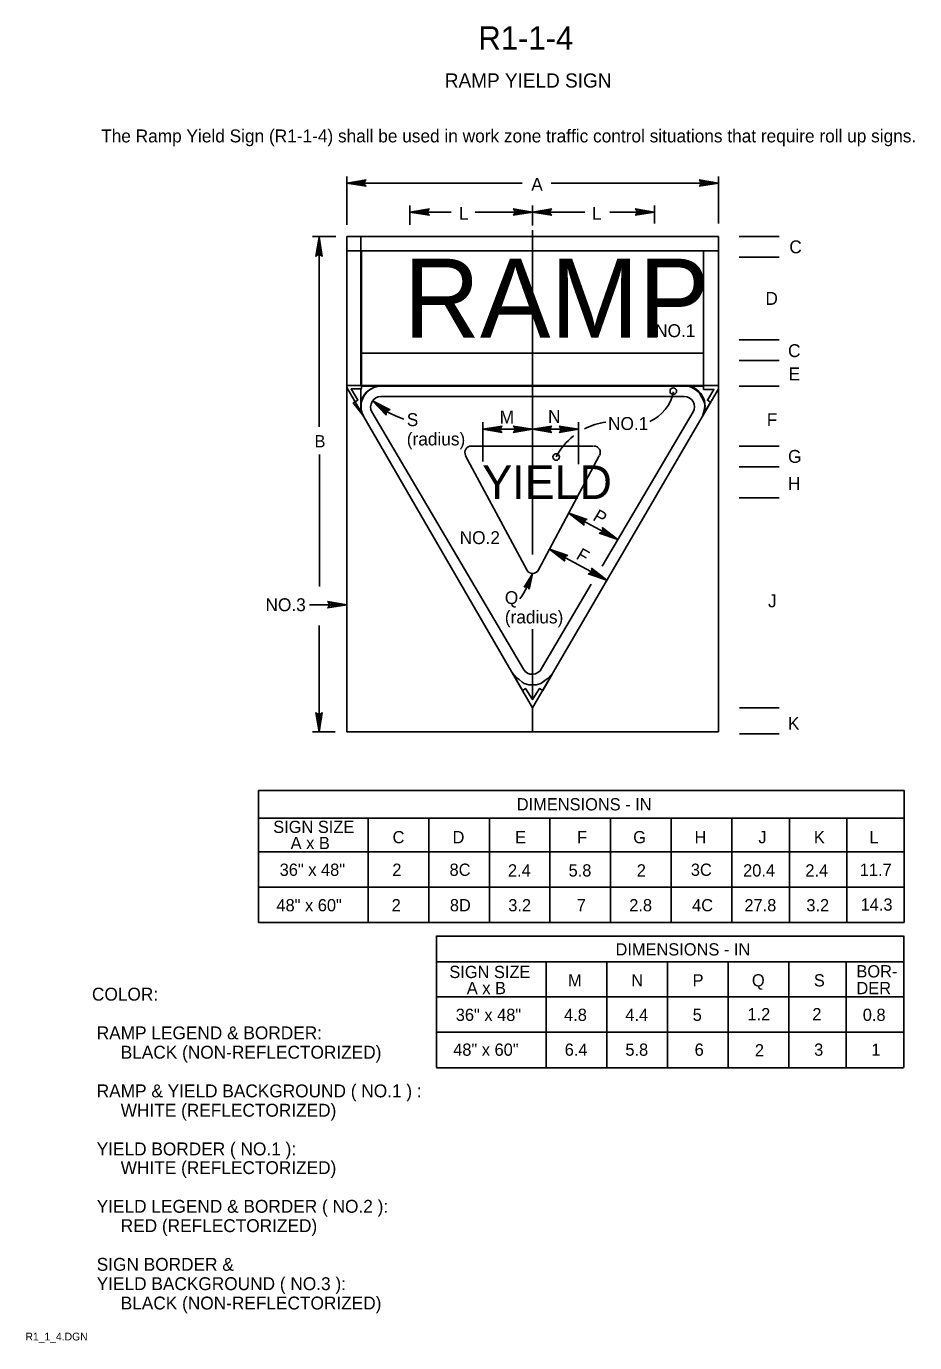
# Model space of a CAD drawing. Extents: x 0.013 to 0.185, y 0.004 to 0.259.
import ezdxf

# ---------------------------------------------------------------- set-up
doc = ezdxf.new("R2010")
doc.units = 0
for name, color, linetype in [('1', 7, 'Continuous'), ('2', 7, 'Continuous'), ('3', 7, 'Continuous')]:
    doc.layers.add(name, color=color, linetype=linetype)

# ---------------------------------------------------------------- blocks, each defined once
blk = doc.blocks.new('RARROW')
at = {"layer": '3'}
for p, q in [((-2.156, 0.28500000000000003), (-2.2665, 0.384625)), ((-2.2665, 0.384625), (0, 0)), ((0, 0), (-2.2665, -0.379125)), ((-2.156, 0.28500000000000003), (-2.075625, 0.12075)), ((0, 0), (-2.156, 0.28500000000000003)), ((-2.14975, -0.2705), (0, 0)), ((-2.075625, 0.12075), (0, 0)), ((0, 0), (-2.074, -0.108)), ((-2.2665, -0.379125), (-2.14975, -0.2705)), ((-2.074, -0.108), (-2.14975, -0.2705))]:
    blk.add_line(p, q, dxfattribs=at)

msp = doc.modelspace()

# ---------------------------------------------------------------- linework, layer by layer
at = {"layer": '1'}
for p, q in [((0.110625, 0.21962500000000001), (0.110625, 0.15675)), ((0.101, 0.182375), (0.101, 0.17475000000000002)), ((0.11950000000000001, 0.182375), (0.11950000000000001, 0.17425000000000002)), ((0.110625, 0.14225000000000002), (0.110625, 0.128625))]:
    msp.add_line(p, q, dxfattribs=at)
at = {"layer": '3'}
for p, q in [((0.074625, 0.22062500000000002), (0.074625, 0.23)), ((0.146625, 0.22087500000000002), (0.146625, 0.23)), ((0.108625, 0.22875), (0.074625, 0.22875)), ((0.11425, 0.22875), (0.146625, 0.22875)), ((0.08687500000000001, 0.22062500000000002), (0.08687500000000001, 0.224375)), ((0.094875, 0.22312500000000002), (0.08687500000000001, 0.22312500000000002)), ((0.0995, 0.22312500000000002), (0.110625, 0.22312500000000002)), ((0.110625, 0.2205), (0.110625, 0.224375)), ((0.12075, 0.22312500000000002), (0.110625, 0.22312500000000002)), ((0.12562500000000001, 0.22312500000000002), (0.13425, 0.22312500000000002)), ((0.13425, 0.22087500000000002), (0.13425, 0.224375)), ((0.0725, 0.218375), (0.068, 0.218375)), ((0.06925, 0.1815), (0.06925, 0.218375)), ((0.074625, 0.218375), (0.074625, 0.122375)), ((0.077375, 0.218375), (0.077375, 0.18962500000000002)), ((0.146625, 0.218375), (0.146625, 0.122375)), ((0.150625, 0.218375), (0.15837500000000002, 0.218375)), ((0.074625, 0.215625), (0.146625, 0.215625)), ((0.150625, 0.214375), (0.15837500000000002, 0.214375)), ((0.150625, 0.198375), (0.15837500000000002, 0.198375)), ((0.150625, 0.194375), (0.15837500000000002, 0.194375)), ((0.074625, 0.1895), (0.077375, 0.1895)), ((0.074625, 0.18912500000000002), (0.110625, 0.127)), ((0.077375, 0.1895), (0.146625, 0.1895)), ((0.078, 0.18937500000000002), (0.14375000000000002, 0.1895)), ((0.146625, 0.18887500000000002), (0.110625, 0.127)), ((0.150625, 0.18937500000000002), (0.15837500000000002, 0.18937500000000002)), ((0.077375, 0.18875), (0.077375, 0.1865)), ((0.08125, 0.187375), (0.14, 0.187375)), ((0.0795, 0.184375), (0.108875, 0.1345)), ((0.14175000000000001, 0.184375), (0.124125, 0.1545)), ((0.101, 0.181), (0.110625, 0.181)), ((0.110625, 0.181), (0.11950000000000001, 0.181)), ((0.06931808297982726, 0.17613725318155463), (0.06931808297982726, 0.15051225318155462)), ((0.098625, 0.17775), (0.122375, 0.17775)), ((0.150625, 0.17775), (0.15837500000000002, 0.17775)), ((0.097625, 0.175875), (0.1095, 0.15375)), ((0.1235, 0.175875), (0.11175, 0.15375)), ((0.150625, 0.17375000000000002), (0.15837500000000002, 0.17375000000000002)), ((0.150625, 0.16775), (0.15837500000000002, 0.16775)), ((0.11762500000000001, 0.16475), (0.12712500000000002, 0.15962500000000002)), ((0.113875, 0.15775), (0.125, 0.15175)), ((0.122, 0.151), (0.112375, 0.134625)), ((0.074625, 0.147), (0.067375, 0.147)), ((0.06925, 0.1429714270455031), (0.06925, 0.122375)), ((0.110625, 0.1315), (0.110625, 0.128625)), ((0.110625, 0.127), (0.110625, 0.122375)), ((0.15075, 0.127), (0.15837500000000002, 0.127)), ((0.072375, 0.122375), (0.068, 0.122375)), ((0.146625, 0.122375), (0.074625, 0.122375)), ((0.09525, 0.122375), (0.146625, 0.122375)), ((0.15075, 0.122), (0.15837500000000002, 0.122)), ((0.0575, 0.111), (0.182625, 0.111)), ((0.0575, 0.111), (0.0575, 0.085375)), ((0.182625, 0.111), (0.182625, 0.085375)), ((0.182625, 0.105625), (0.0575, 0.105625)), ((0.07879158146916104, 0.10562213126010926), (0.07879158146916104, 0.08537213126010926)), ((0.0905, 0.105625), (0.0905, 0.085375)), ((0.10225000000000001, 0.105625), (0.10225000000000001, 0.085375)), ((0.114, 0.105625), (0.114, 0.085375)), ((0.12575, 0.105625), (0.12575, 0.085375)), ((0.1375, 0.105625), (0.1375, 0.085375)), ((0.14925, 0.105625), (0.14925, 0.085375)), ((0.160375, 0.105625), (0.160375, 0.085375)), ((0.1715, 0.105625), (0.1715, 0.085375)), ((0.0575, 0.099125), (0.182625, 0.099125)), ((0.0575, 0.09225), (0.182625, 0.09225)), ((0.0575, 0.085375), (0.182625, 0.085375)), ((0.092, 0.08275), (0.1825, 0.08275)), ((0.09204158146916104, 0.08278405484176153), (0.09204158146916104, 0.05728405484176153)), ((0.18254158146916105, 0.08278405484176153), (0.18254158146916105, 0.05728405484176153)), ((0.1825, 0.07775), (0.092, 0.07775)), ((0.11329158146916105, 0.07778405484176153), (0.11329158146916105, 0.05728405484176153)), ((0.125, 0.07775), (0.125, 0.05725)), ((0.13675, 0.07775), (0.13675, 0.05725)), ((0.1485, 0.07775), (0.1485, 0.05725)), ((0.16025, 0.07775), (0.16025, 0.05725)), ((0.17141658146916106, 0.07778405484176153), (0.17141658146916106, 0.05728405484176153)), ((0.092, 0.07100000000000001), (0.1825, 0.07100000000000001)), ((0.092, 0.064125), (0.1825, 0.064125)), ((0.092, 0.05725), (0.1825, 0.05725))]:
    msp.add_line(p, q, dxfattribs=at)
for points in [[(0.074625, 0.218375), (0.146625, 0.218375), (0.146625, 0.215625), (0.074625, 0.215625)], [(0.074625, 0.215625), (0.0775, 0.215625), (0.0775, 0.1895), (0.074625, 0.1895)], [(0.14375000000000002, 0.215625), (0.146625, 0.215625), (0.146625, 0.1895), (0.14375000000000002, 0.1895)], [(0.0775, 0.18937500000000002), (0.14375000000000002, 0.18937500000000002), (0.14375000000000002, 0.19575), (0.0775, 0.19575)], [(0.074625, 0.18912500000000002), (0.110625, 0.127), (0.110625, 0.122375), (0.074625, 0.122375)], [(0.0775, 0.1895), (0.0775, 0.18887500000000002), (0.0755, 0.18887500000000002), (0.07675, 0.186625), (0.075875, 0.186125), (0.07775, 0.18375), (0.0775, 0.1845), (0.077375, 0.185), (0.077375, 0.185375), (0.077375, 0.18625), (0.077375, 0.18625), (0.077375, 0.186375), (0.077375, 0.186375), (0.077625, 0.187), (0.07775, 0.18725), (0.077875, 0.1875), (0.078375, 0.18812500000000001), (0.079125, 0.18875), (0.079875, 0.18912500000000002), (0.081, 0.1895)], [(0.146625, 0.18887500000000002), (0.146625, 0.122375), (0.110625, 0.122375), (0.110625, 0.127)], [(0.14375000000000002, 0.1895), (0.14375000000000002, 0.18875), (0.14575, 0.18875), (0.1445, 0.186625), (0.145125, 0.18625), (0.143625, 0.18375), (0.143875, 0.184625), (0.14400000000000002, 0.1855), (0.14400000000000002, 0.18575), (0.143875, 0.18625), (0.143625, 0.186875), (0.14325000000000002, 0.1875), (0.142875, 0.18812500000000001), (0.142125, 0.18875), (0.14150000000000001, 0.18912500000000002), (0.1405, 0.1895)], [(0.110625, 0.1315), (0.111375, 0.1315), (0.11225, 0.13175), (0.11325, 0.1325), (0.113625, 0.13275), (0.114625, 0.133875), (0.11259853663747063, 0.13038704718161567), (0.112, 0.13075), (0.110625, 0.128625)]]:
    msp.add_lwpolyline(points, close=True, dxfattribs=at)
for points in [[(0.110625, 0.128625), (0.10925, 0.13075), (0.10866220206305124, 0.1303912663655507), (0.10664205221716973, 0.13387545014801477), (0.107625, 0.13275), (0.108, 0.1325), (0.108625, 0.132), (0.109, 0.13175), (0.109875, 0.1315), (0.110625, 0.1315)], [(0.110625, 0.128625), (0.112, 0.13075), (0.11259853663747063, 0.13038704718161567), (0.114625, 0.133875), (0.113625, 0.13275), (0.11325, 0.1325), (0.112625, 0.132), (0.11225, 0.13175), (0.111375, 0.1315), (0.110625, 0.1315)]]:
    msp.add_lwpolyline(points, dxfattribs=at)
for centre in [(0.13789616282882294, 0.18840253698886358), (0.11519308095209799, 0.17563725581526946)]:
    msp.add_circle(centre, 0.000637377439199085, dxfattribs=at)
for centre, radius, start, end in [((0.08136421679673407, 0.18541406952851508), 0.003973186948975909, 89.96691944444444, 208.09065555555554), ((0.14000640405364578, 0.18546427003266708), 0.004048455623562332, 331.0033472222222, 89.12708333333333), ((0.08127427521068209, 0.18535042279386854), 0.0020247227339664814, 90.68695833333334, 208.80016666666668), ((0.09065062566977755, 0.19855597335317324), 0.016337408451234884, 227.5559497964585, 252.3694840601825), ((0.13001534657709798, 0.18990385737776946), 0.008095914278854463, 294.0761694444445, 348.30106111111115), ((0.13997572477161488, 0.18535042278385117), 0.002024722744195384, 331.19983333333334, 89.31304166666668), ((0.1265201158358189, 0.16972301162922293), 0.01277810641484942, 97.65450833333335, 117.01230000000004), ((0.1265201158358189, 0.16972301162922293), 0.01277810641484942, 128.53098888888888, 152.42935277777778), ((0.09875515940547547, 0.17651225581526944), 0.00125, 90.00000000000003, 207.55281111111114), ((0.1224949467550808, 0.17651225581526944), 0.00125, 332.17590277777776, 90), ((0.11062500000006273, 0.1543371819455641), 0.0012690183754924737, 207.56183611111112, 332.4381666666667), ((0.09242133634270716, 0.15909322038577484), 0.01920287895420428, 325.13440408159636, 341.53859738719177), ((0.11059163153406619, 0.135496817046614), 0.001985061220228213, 210.14296388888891, 333.9478527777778)]:
    msp.add_arc(centre, radius, start, end, dxfattribs=at)

# ---------------------------------------------------------------- block references
for p, xscale, yscale, rotation in [((0.074625, 0.22875), 0.0016545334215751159, 0.0016366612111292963, 180), ((0.08687500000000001, 0.22312500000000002), 0.0016545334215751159, 0.0016366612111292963, 180), ((0.110625, 0.22312500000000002), 0.0016545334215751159, 0.0016366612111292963, 180), ((0.06925, 0.21825), 0.0016545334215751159, 0.0016366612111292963, 90), ((0.079625, 0.1865), 0.0016545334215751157, 0.0016366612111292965, 143.79741070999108), ((0.101, 0.181), 0.0016545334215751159, 0.0016366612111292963, 180), ((0.110625, 0.181), 0.0016545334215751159, 0.0016366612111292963, 180), ((0.11762500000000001, 0.16475), 0.0016545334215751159, 0.0016366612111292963, 151.92751306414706), ((0.12712500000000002, 0.15962500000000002), 0.0016545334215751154, -0.0016366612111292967, -28.61898862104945), ((0.113875, 0.15775), 0.0016545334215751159, 0.0016366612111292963, 151.92751306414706), ((0.110625, 0.153), 0.001340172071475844, 0.0013256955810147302, 67.86539075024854), ((0.125, 0.15175), 0.0016545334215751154, -0.0016366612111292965, -28.982116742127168), ((0.06925, 0.122375), 0.0016545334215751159, 0.0016366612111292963, -90)]:
    msp.add_blockref('RARROW', p, dxfattribs=dict(at, xscale=xscale, yscale=yscale, rotation=rotation))
at = {"layer": '3', "xscale": 0.0016545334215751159, "yscale": 0.0016366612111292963}
for p in [(0.146625, 0.22875), (0.110625, 0.22312500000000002), (0.13425, 0.22312500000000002), (0.110625, 0.181), (0.11950000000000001, 0.181), (0.074625, 0.147)]:
    msp.add_blockref('RARROW', p, dxfattribs=at)

# ---------------------------------------------------------------- texts
at = {"layer": '1'}
for s, height, p in [('R1-1-4', 0.0045000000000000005, (0.100125, 0.254625)), ('RAMP YIELD SIGN', 0.00275025, (0.093625, 0.24725)), ('COLOR:', 0.0024997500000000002, (0.02525, 0.07025)), (' RAMP LEGEND & BORDER:', 0.0024997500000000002, (0.02525, 0.06275)), ('      BLACK (NON-REFLECTORIZED)', 0.0024997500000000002, (0.02525, 0.059000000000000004)), (' RAMP & YIELD BACKGROUND ( NO.1 ) :', 0.0024997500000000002, (0.02525, 0.051500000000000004)), ('      WHITE (REFLECTORIZED)', 0.0024997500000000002, (0.02525, 0.04775)), (' YIELD BORDER ( NO.1 ):', 0.0024997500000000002, (0.02525, 0.04025)), ('      WHITE (REFLECTORIZED)', 0.0024997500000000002, (0.02525, 0.036625)), (' YIELD LEGEND & BORDER ( NO.2 ):', 0.0024997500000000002, (0.02525, 0.029125)), ('      RED (REFLECTORIZED)', 0.0024997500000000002, (0.02525, 0.025375)), (' SIGN BORDER &', 0.0024997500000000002, (0.02525, 0.017875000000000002)), (' YIELD BACKGROUND ( NO.3 ):', 0.0024997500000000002, (0.02525, 0.014125)), ('      BLACK (NON-REFLECTORIZED)', 0.0024997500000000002, (0.02525, 0.010375)), ('R1_1_4.DGN', 0.0015, (0.012375, 0.004375))]:
    msp.add_text(s, height=height, dxfattribs=at).set_placement(p)
at = {"layer": '2'}
msp.add_text('   The Ramp Yield Sign (R1-1-4) shall be used in work zone traffic control situations that require roll up signs.', height=0.0024997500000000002, dxfattribs=at).set_placement((0.02425, 0.236625))
at = {"layer": '3'}
for s, height, p in [('A', 0.0024997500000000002, (0.110375, 0.22725)), ('L', 0.0024997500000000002, (0.096375, 0.22162500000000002)), ('L', 0.0024997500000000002, (0.122125, 0.22162500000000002)), ('C', 0.0024997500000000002, (0.160375, 0.215125)), ('RAMP', 0.01533, (0.085625, 0.19875)), ('D', 0.0024997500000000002, (0.15575, 0.205125)), ('NO.1', 0.0024997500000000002, (0.134375, 0.198875)), ('C', 0.0024997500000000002, (0.160125, 0.195)), ('E', 0.0024997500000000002, (0.16025, 0.1905)), ('S', 0.0024997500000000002, (0.08625000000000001, 0.181625)), ('M', 0.0024997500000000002, (0.10425, 0.182125)), ('N', 0.0024997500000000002, (0.113625, 0.18225)), ('F', 0.0024997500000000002, (0.156, 0.181625)), ('NO.1', 0.0024997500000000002, (0.12525, 0.180875)), ('B', 0.0023752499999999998, (0.068375, 0.1775)), ('(radius)', 0.0024997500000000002, (0.08625000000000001, 0.177875)), ('G', 0.0024997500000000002, (0.160125, 0.17450000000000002)), ('YIELD', 0.006500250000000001, (0.100875, 0.1675)), ('H', 0.0024997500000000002, (0.160125, 0.16925)), ('NO.2', 0.0024997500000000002, (0.0965, 0.15875)), ('NO.3', 0.0024997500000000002, (0.058875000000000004, 0.14575)), ('Q', 0.0024997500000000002, (0.10525, 0.147125)), ('J', 0.0024997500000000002, (0.15625, 0.1465)), ('(radius)', 0.0024997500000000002, (0.10525, 0.143375)), ('K', 0.0024997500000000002, (0.160125, 0.12275)), ('DIMENSIONS - IN', 0.0023752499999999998, (0.10756659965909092, 0.107125)), ('SIGN SIZE', 0.0023752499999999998, (0.060375, 0.10275000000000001)), ('C', 0.0023752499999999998, (0.0835, 0.10075)), ('D', 0.0023752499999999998, (0.095125, 0.10075)), ('E', 0.0023752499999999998, (0.10725, 0.10075)), ('F', 0.0023752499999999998, (0.11925000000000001, 0.10075)), ('G', 0.0023752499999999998, (0.130125, 0.10075)), ('H', 0.0023752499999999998, (0.14200000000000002, 0.10075)), ('J', 0.0023752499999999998, (0.154375, 0.10075)), ('K', 0.0023752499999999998, (0.165125, 0.10075)), ('L', 0.0023752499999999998, (0.175875, 0.10075)), ('A x B', 0.0023752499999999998, (0.06375, 0.099625)), ('36" x 48"', 0.0023752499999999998, (0.06162041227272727, 0.094437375)), ('2', 0.0023752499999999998, (0.08344853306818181, 0.094437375)), ('8C', 0.0023752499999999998, (0.09453957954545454, 0.094437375)), ('2.4', 0.0023752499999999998, (0.10585699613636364, 0.094312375)), ('5.8', 0.0023752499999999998, (0.11760555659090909, 0.094312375)), ('2', 0.0023752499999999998, (0.13082353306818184, 0.094312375)), ('3C', 0.0023752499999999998, (0.14128957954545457, 0.094437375)), ('20.4', 0.0023752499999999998, (0.15142129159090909, 0.094312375)), ('2.4', 0.0023752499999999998, (0.16348199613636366, 0.094312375)), ('11.7', 0.0023752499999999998, (0.1740253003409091, 0.094437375)), ('48" x 60"', 0.0023752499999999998, (0.06099541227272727, 0.087562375)), ('2', 0.0023752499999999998, (0.08332353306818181, 0.087562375)), ('8D', 0.0023752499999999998, (0.09459656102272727, 0.087562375)), ('3.2', 0.0023752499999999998, (0.10591997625, 0.087562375)), ('7', 0.0023752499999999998, (0.11918269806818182, 0.087562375)), ('2.8', 0.0023752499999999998, (0.12935555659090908, 0.087562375)), ('4C', 0.0023752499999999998, (0.14153957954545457, 0.087562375)), ('27.8', 0.0023752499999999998, (0.15166985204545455, 0.087562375)), ('3.2', 0.0023752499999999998, (0.16366997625, 0.087562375)), ('14.3', 0.0023752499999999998, (0.17418328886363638, 0.087687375)), ('DIMENSIONS - IN', 0.0023752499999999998, (0.1266915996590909, 0.079)), ('SIGN SIZE', 0.0023752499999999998, (0.0945, 0.074625)), ('BOR-', 0.0023752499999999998, (0.173375, 0.07475)), ('M', 0.0023752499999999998, (0.11750000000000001, 0.073)), ('N', 0.0023752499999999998, (0.12975, 0.073)), ('P', 0.0023752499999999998, (0.141625, 0.073)), ('Q', 0.0023752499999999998, (0.153125, 0.073)), ('S', 0.0023752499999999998, (0.165125, 0.073)), ('A x B', 0.0023752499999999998, (0.097875, 0.07150000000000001)), ('DER', 0.0023752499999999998, (0.173375, 0.07150000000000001)), ('36" x 48"', 0.0023752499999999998, (0.09574541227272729, 0.066312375)), ('4.8', 0.0023752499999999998, (0.11673055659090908, 0.066312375)), ('4.4', 0.0023752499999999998, (0.12860699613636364, 0.066312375)), ('5', 0.0023752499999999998, (0.14164994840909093, 0.066312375)), ('1.2', 0.0023752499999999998, (0.15226090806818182, 0.066437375)), ('2', 0.0023752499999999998, (0.16482353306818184, 0.066437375)), ('0.8', 0.0023752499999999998, (0.1746055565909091, 0.066312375)), ('48" x 60"', 0.0023752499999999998, (0.09524541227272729, 0.059562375)), ('6.4', 0.0023752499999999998, (0.11685699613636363, 0.059562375)), ('5.8', 0.0023752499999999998, (0.12860555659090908, 0.059562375)), ('6', 0.0023752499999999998, (0.14202206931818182, 0.059562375)), ('2', 0.0023752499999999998, (0.15369853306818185, 0.05943737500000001)), ('3', 0.0023752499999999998, (0.1651816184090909, 0.059562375)), ('1', 0.0023752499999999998, (0.1762704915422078, 0.059562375))]:
    msp.add_text(s, height=height, dxfattribs=at).set_placement(p)
for s, height, p in [('P', 0.0024990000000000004, (0.122125, 0.1635)), ('F', 0.0024997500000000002, (0.11887500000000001, 0.156))]:
    msp.add_text(s, height=height, rotation=329.34123611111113, dxfattribs=at).set_placement(p)

doc.saveas('drawing.dxf')
